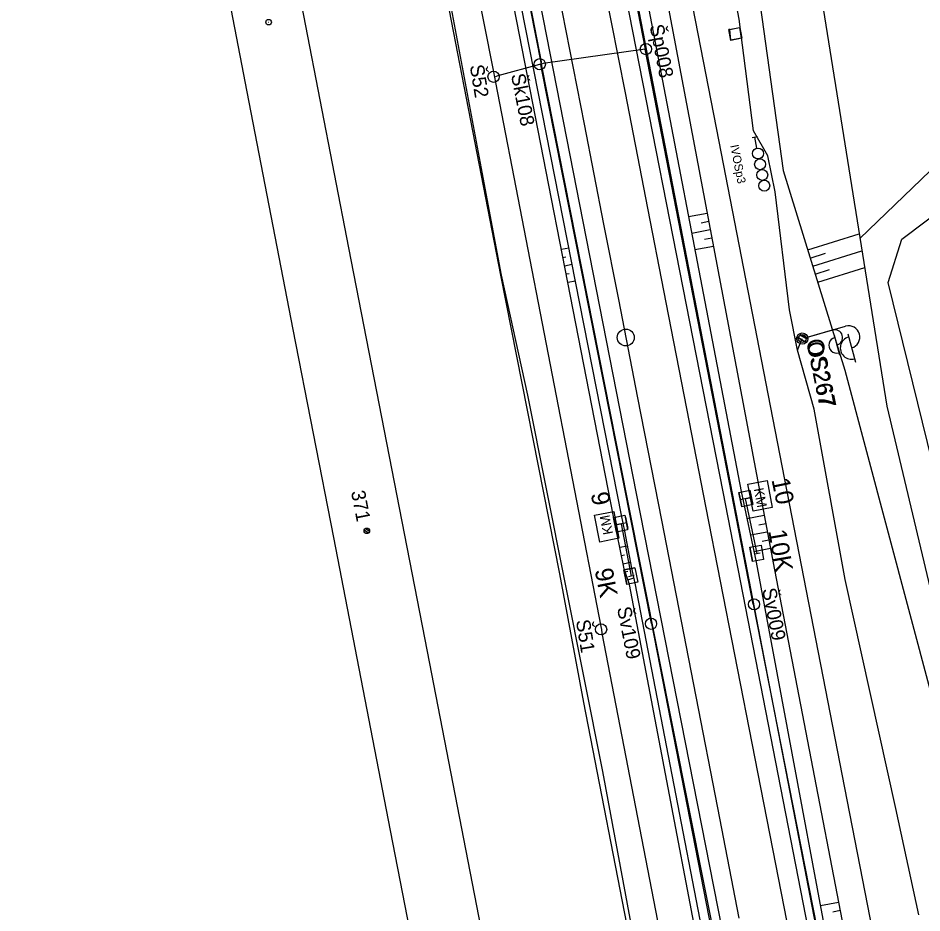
# Model space of a CAD drawing. Extents: x -545967 to -545044, y -1122650 to -1118491.
# Drawn here: x -545851.2 to -545770.8, y -1118840.2 to -1118760.6 of the extents above; entities that cross this region are included whole.
import ezdxf

# ---------------------------------------------------------------- set-up
doc = ezdxf.new("R2010")
doc.units = 0
for name, color, linetype in [('Vrstva 1', 7, 'Continuous'), ('Vrstva 1 - Koleje', 7, 'Continuous'), ('Vrstva 11', 7, 'Continuous'), ('Vrstva 11 - Trakce', 7, 'Continuous'), ('Vrstva 12', 7, 'Continuous'), ('Vrstva 12 - Trakce zaklady', 7, 'Continuous'), ('Vrstva 19 - Staniceni', 7, 'Continuous'), ('Vrstva 25', 7, 'Continuous'), ('Vrstva 25 - silnoproud prvky', 7, 'Continuous'), ('Vrstva 26', 7, 'Continuous'), ('Vrstva 26 - silnoproud', 7, 'Continuous'), ('Vrstva 28', 7, 'Continuous'), ('Vrstva 28 - zabzar', 7, 'Continuous'), ('Vrstva 32', 7, 'Continuous'), ('Vrstva 4 - Teren - stezky - prechody - plochy', 7, 'Continuous'), ('Vrstva 43', 7, 'Continuous'), ('Vrstva 44', 7, 'Continuous'), ('Vrstva 48', 7, 'Continuous'), ('Vrstva 49', 7, 'Continuous'), ('Vrstva 6', 7, 'Continuous'), ('Vrstva 62', 7, 'Continuous')]:
    doc.layers.add(name, color=color, linetype=linetype)

msp = doc.modelspace()

# ---------------------------------------------------------------- linework, layer by layer
at = {"layer": 'Vrstva 1'}
for points in [[(-545803.343, -1118697.361), (-545802.529, -1118701.559), (-545796.372, -1118733.137), (-545788.892, -1118771.626), (-545784.123, -1118796.192), (-545777.723, -1118829.089), (-545771.163, -1118862.699), (-545764.792, -1118895.381), (-545757.603, -1118932.309), (-545753.441, -1118953.648), (-545749.904, -1118971.286), (-545746.403, -1118987.4), (-545742.64, -1119003.664), (-545739.307, -1119017.411), (-545735.997, -1119030.103), (-545730.526, -1119049.438)], [(-545838.408, -1118714.766), (-545838.264, -1118718.348), (-545837.486, -1118728.28), (-545836.887, -1118733.389), (-545834.73, -1118746.875), (-545830.836, -1118767.188), (-545826.73, -1118788.319), (-545823.138, -1118806.831), (-545818.076, -1118832.894), (-545813.108, -1118858.452), (-545808.531, -1118881.987), (-545803.057, -1118910.121), (-545797.597, -1118938.248), (-545792.143, -1118966.396), (-545787.423, -1118990.652), (-545782.57, -1119015.553), (-545777.212, -1119042.997), (-545771.689, -1119071.297)], [(-545838.408, -1118714.766), (-545838.264, -1118718.348), (-545837.486, -1118728.28), (-545836.887, -1118733.389), (-545834.73, -1118746.875), (-545830.836, -1118767.188), (-545826.73, -1118788.319), (-545823.138, -1118806.831), (-545818.076, -1118832.894), (-545813.108, -1118858.452), (-545808.531, -1118881.987), (-545803.057, -1118910.121), (-545797.597, -1118938.248), (-545792.143, -1118966.396), (-545787.423, -1118990.652), (-545782.57, -1119015.553), (-545777.212, -1119042.997), (-545771.689, -1119071.297)], [(-545833.035, -1118722.987), (-545832.612, -1118725.218), (-545828.16, -1118748.155), (-545821.787, -1118781.064), (-545814.8, -1118816.973), (-545807.184, -1118856.232), (-545801.349, -1118886.259), (-545795.986, -1118913.812), (-545789.887, -1118945.221), (-545784.095, -1118975.016), (-545776.352, -1119014.883), (-545771.025, -1119042.195)]]:
    msp.add_lwpolyline(points, dxfattribs=at)
at = {"layer": 'Vrstva 1 - Koleje'}
for points in [[(-545809.67, -1118703.454), (-545807.882, -1118712.632), (-545806.03, -1118722.125), (-545804.223, -1118731.391), (-545802.337, -1118741.068), (-545800.493, -1118750.516), (-545799.063, -1118757.843), (-545797.222, -1118767.299), (-545795.407, -1118776.622), (-545793.591, -1118785.937), (-545791.761, -1118795.345), (-545790.039, -1118804.177), (-545787.497, -1118817.223), (-545785.692, -1118826.488), (-545783.856, -1118835.888), (-545781.902, -1118845.893)], [(-545812.52, -1118710.222), (-545810.747, -1118719.317), (-545808.924, -1118728.683), (-545807.065, -1118738.215), (-545804.558, -1118751.082), (-545802.792, -1118760.131), (-545800.853, -1118770.074), (-545799.124, -1118778.962), (-545797.814, -1118785.665), (-545796.111, -1118794.424), (-545793.992, -1118805.28), (-545790.937, -1118820.957), (-545789.005, -1118830.866), (-545787.094, -1118840.68)]]:
    msp.add_lwpolyline(points, dxfattribs=at)
at = {"layer": 'Vrstva 11'}
for p, q in [((-545820.029, -1118806.446), (-545820.407, -1118806.19)), ((-545819.921, -1118806.292), (-545820.305, -1118806.033))]:
    msp.add_line(p, q, dxfattribs=at)
msp.add_circle((-545820.163, -1118806.237), 0.25, dxfattribs=at)
at = {"layer": 'Vrstva 11 - Trakce'}
for p, q in [((-545787.097, -1118802.985), (-545786.892, -1118803.964)), ((-545786.118, -1118802.78), (-545785.913, -1118803.759)), ((-545786.016, -1118803.269), (-545786.994, -1118803.475)), ((-545785.473, -1118808.256), (-545786.505, -1118803.372)), ((-545798.152, -1118805.226), (-545797.959, -1118806.207)), ((-545797.171, -1118805.033), (-545796.978, -1118806.014)), ((-545797.074, -1118805.523), (-545798.056, -1118805.717)), ((-545797.565, -1118805.62), (-545796.668, -1118810.265)), ((-545785.224, -1118808.213), (-545785.716, -1118808.298)), ((-545796.42, -1118810.216), (-545796.91, -1118810.313))]:
    msp.add_line(p, q, dxfattribs=at)
at = {"layer": 'Vrstva 12'}
msp.add_line((-545787.822, -1118762.641), (-545788.002, -1118761.65), dxfattribs=at)
for points in [[(-545787.906, -1118761.663), (-545788.002, -1118761.65), (-545787.025, -1118761.482), (-545787.051, -1118761.467)], [(-545787.025, -1118761.482), (-545786.835, -1118762.42), (-545786.886, -1118762.435)], [(-545786.835, -1118762.42), (-545787.822, -1118762.641), (-545787.806, -1118762.593)]]:
    msp.add_lwpolyline(points, dxfattribs=at)
msp.add_lwpolyline([(-545787.906, -1118761.663), (-545787.051, -1118761.467), (-545786.886, -1118762.435), (-545787.806, -1118762.593)], close=True, dxfattribs=at)
at = {"layer": 'Vrstva 12 - Trakce zaklady'}
for p, q in [((-545787.117, -1118802.83), (-545786.138, -1118802.625)), ((-545785.871, -1118803.897), (-545786.85, -1118804.102)), ((-545798.231, -1118805.05), (-545797.25, -1118804.857)), ((-545796.994, -1118806.157), (-545797.975, -1118806.35)), ((-545786.122, -1118807.675), (-545785.137, -1118807.504)), ((-545784.913, -1118808.794), (-545785.898, -1118808.965)), ((-545796.339, -1118809.519), (-545797.32, -1118809.713)), ((-545796.084, -1118810.808), (-545797.065, -1118811.002))]:
    msp.add_line(p, q, dxfattribs=at)
for points in [[(-545786.85, -1118804.102), (-545787.117, -1118802.83), (-545786.138, -1118802.625), (-545785.871, -1118803.897), (-545786.85, -1118804.102)], [(-545787.117, -1118802.83), (-545787.117, -1118802.83), (-545786.85, -1118804.102), (-545786.85, -1118804.102)], [(-545786.138, -1118802.625), (-545786.138, -1118802.625), (-545785.871, -1118803.897), (-545785.871, -1118803.897)], [(-545797.25, -1118804.857), (-545796.994, -1118806.157), (-545797.975, -1118806.35), (-545798.231, -1118805.05), (-545797.25, -1118804.857)], [(-545798.231, -1118805.05), (-545798.231, -1118805.05), (-545797.975, -1118806.35), (-545797.975, -1118806.35)], [(-545797.25, -1118804.857), (-545797.25, -1118804.857), (-545796.994, -1118806.157), (-545796.994, -1118806.157)], [(-545785.898, -1118808.965), (-545786.122, -1118807.675), (-545785.137, -1118807.504), (-545784.913, -1118808.794), (-545785.898, -1118808.965)], [(-545786.122, -1118807.675), (-545786.122, -1118807.675), (-545785.898, -1118808.965), (-545785.898, -1118808.965)], [(-545785.137, -1118807.504), (-545785.137, -1118807.504), (-545784.913, -1118808.794), (-545784.913, -1118808.794)], [(-545796.339, -1118809.519), (-545796.084, -1118810.808), (-545797.065, -1118811.002), (-545797.32, -1118809.713), (-545796.339, -1118809.519)], [(-545797.32, -1118809.713), (-545797.32, -1118809.713), (-545797.065, -1118811.002), (-545797.065, -1118811.002)], [(-545796.339, -1118809.519), (-545796.339, -1118809.519), (-545796.084, -1118810.808), (-545796.084, -1118810.808)]]:
    msp.add_lwpolyline(points, dxfattribs=at)
at = {"layer": 'Vrstva 19 - Staniceni'}
for p, q in [((-545786.505, -1118803.372), (-545786.077, -1118803.289)), ((-545797.565, -1118805.62), (-545797.993, -1118805.704))]:
    msp.add_line(p, q, dxfattribs=at)
for points in [[(-545786.308, -1118802.092), (-545784.602, -1118801.762), (-545784.138, -1118804.159), (-545785.845, -1118804.489)], [(-545797.759, -1118806.9), (-545799.465, -1118807.233), (-545799.933, -1118804.837), (-545798.227, -1118804.504)]]:
    msp.add_lwpolyline(points, close=True, dxfattribs=at)
msp.add_circle((-545797.157, -1118789.046), 0.75, dxfattribs=at)
at = {"layer": 'Vrstva 25'}
for p, q in [((-545780.992, -1118789.001), (-545777.623, -1118788.05)), ((-545781.958, -1118789.026), (-545781.123, -1118789.493)), ((-545781.743, -1118788.717), (-545780.976, -1118789.146)), ((-545777.433, -1118788.724), (-545776.727, -1118791.226))]:
    msp.add_line(p, q, dxfattribs=at)
msp.add_circle((-545781.473, -1118789.137), 0.5, dxfattribs=at)
msp.add_circle((-545781.473, -1118789.137), 0.5, dxfattribs=at)
for centre, start, end in [((-545777.352, -1118789.013), 285.76362, 105.76362), ((-545777.092, -1118789.978), 105.06104, 286.46619)]:
    msp.add_arc(centre, 1, start, end, dxfattribs=at)
at = {"layer": 'Vrstva 25 - silnoproud prvky'}
for p, q in [((-545781.136, -1118789.042), (-545778.778, -1118788.376)), ((-545781.813, -1118789.059), (-545781.228, -1118789.386)), ((-545781.662, -1118788.843), (-545781.125, -1118789.143)), ((-545778.645, -1118788.848), (-545778.151, -1118790.599))]:
    msp.add_line(p, q, dxfattribs=at)
msp.add_circle((-545781.473, -1118789.137), 0.35, dxfattribs=at)
for centre, start, end in [((-545778.588, -1118789.05), 285.76362, 105.76362), ((-545778.406, -1118789.726), 105.06104, 286.46619)]:
    msp.add_arc(centre, 0.7, start, end, dxfattribs=at)
at = {"layer": 'Vrstva 26'}
for points in [[(-545771.097, -1118840.383), (-545773.141, -1118830.925), (-545777.672, -1118810.574), (-545780.401, -1118795.417), (-545781.883, -1118790.167), (-545782.61, -1118786.576), (-545783.878, -1118776.094), (-545784.515, -1118772.9), (-545785.804, -1118770.659), (-545787.081, -1118760.752), (-545789.369, -1118748.588), (-545791.737, -1118737.523), (-545792.399, -1118734.644), (-545793.816, -1118727.544), (-545794.532, -1118722.759), (-545794.625, -1118720.933), (-545795.14, -1118719.856), (-545797.401, -1118709.038)], [(-545781.883, -1118790.167), (-545781.473, -1118789.137)]]:
    msp.add_lwpolyline(points, dxfattribs=at)
at = {"layer": 'Vrstva 26 - silnoproud'}
for points in [[(-545804.723, -1118669.38), (-545823.422, -1118673.004), (-545824.024, -1118671.607), (-545826.19, -1118672.019), (-545826.479, -1118672.345), (-545826.082, -1118675.405), (-545825.636, -1118675.016), (-545825.253, -1118675.052), (-545825.524, -1118675.387), (-545825.985, -1118675.439), (-545827.078, -1118675.764), (-545828.843, -1118676.437), (-545828.656, -1118678.804), (-545827.868, -1118683.721), (-545826.321, -1118691.367), (-545821.946, -1118713.57), (-545816.92, -1118739.132), (-545813.046, -1118758.857), (-545808.289, -1118783.504), (-545803.049, -1118810.067), (-545800.897, -1118821.514), (-545796.684, -1118843.318)], [(-545771.097, -1118840.383), (-545773.141, -1118830.925), (-545777.672, -1118810.574), (-545780.401, -1118795.417), (-545781.883, -1118790.167), (-545782.61, -1118786.576), (-545783.878, -1118776.094), (-545784.515, -1118772.9), (-545785.804, -1118770.659), (-545787.081, -1118760.752), (-545789.369, -1118748.588), (-545791.737, -1118737.523), (-545792.399, -1118734.644), (-545793.816, -1118727.544), (-545794.532, -1118722.759), (-545794.625, -1118720.933), (-545795.14, -1118719.856), (-545797.401, -1118709.038)], [(-545781.883, -1118790.167), (-545781.473, -1118789.137)]]:
    msp.add_lwpolyline(points, dxfattribs=at)
at = {"layer": 'Vrstva 28'}
msp.add_line((-545828.914, -1118761.007), (-545828.864, -1118761.007), dxfattribs=at)
msp.add_circle((-545828.889, -1118761.007), 0.25, dxfattribs=at)
at = {"layer": 'Vrstva 28 - zabzar'}
msp.add_lwpolyline([(-545759.72, -1119031.91), (-545759.89, -1119030.77), (-545763.23, -1119013.33), (-545766.25, -1118997.62), (-545768.86, -1118984.55), (-545771, -1118974.69), (-545771.8, -1118970.9), (-545773.86, -1118959.07), (-545776.3, -1118946.17), (-545780.31, -1118924.98), (-545785.87, -1118897.11), (-545790.99, -1118870.65), (-545796.29, -1118843.25), (-545799.19, -1118827.63), (-545805.85, -1118794.17), (-545808.2, -1118783.5), (-545812.82, -1118758.82), (-545816.62, -1118739.16), (-545820.43, -1118719.58), (-545822.89, -1118707.67), (-545825.23, -1118696.09)], dxfattribs=at)
at = {"layer": 'Vrstva 32'}
msp.add_lwpolyline([(-545796.29, -1118843.25), (-545799.19, -1118827.63), (-545805.85, -1118794.17), (-545808.2, -1118783.5), (-545812.82, -1118758.82), (-545816.62, -1118739.16), (-545820.43, -1118719.58), (-545822.89, -1118707.67)], dxfattribs=at)
at = {"layer": 'Vrstva 4 - Teren - stezky - prechody - plochy'}
for points in [[(-545842.991, -1118523.919), (-545841.705, -1118530.396), (-545836.849, -1118554.447), (-545831.054, -1118584.604), (-545819.351, -1118645.264), (-545811.232, -1118686.911), (-545799.532, -1118746.647), (-545788.535, -1118802.768), (-545777.847, -1118857.696), (-545765.826, -1118919.341), (-545755.98, -1118970.183), (-545745.509, -1119023.121), (-545734.813, -1119078.883), (-545723.148, -1119138.675), (-545711.327, -1119199.256), (-545707.51, -1119218.932), (-545706.355, -1119218.803)], [(-545842.057, -1118523.737), (-545841.08, -1118528.803), (-545840.285, -1118532.869), (-545839.902, -1118534.493), (-545835.95, -1118554.692), (-545830.173, -1118584.852), (-545827.402, -1118599.381), (-545819.669, -1118640.626), (-545818.68, -1118644.829), (-545817.556, -1118652.409), (-545817.153, -1118653.253), (-545814.795, -1118664.646), (-545810.716, -1118686.202), (-545798.466, -1118747.292), (-545787.709, -1118802.92), (-545777.141, -1118857.583)], [(-545711.324, -1119247.435), (-545711.901, -1119243.963), (-545720.224, -1119201.665), (-545721.285, -1119195.757), (-545731.546, -1119141.712), (-545737.081, -1119112.42), (-545743.441, -1119079.103), (-545754.278, -1119022.005), (-545764.127, -1118971.243), (-545774.702, -1118917.119), (-545786.098, -1118858.181), (-545797.005, -1118803.413), (-545807.661, -1118749.422), (-545819.911, -1118686.431), (-545828.531, -1118641.36), (-545850.15, -1118530.525), (-545851.156, -1118525.517)], [(-545710.225, -1119247.22), (-545719.004, -1119201.386), (-545730.622, -1119141.385), (-545736.208, -1119112.206), (-545742.564, -1119078.927), (-545753.414, -1119021.814), (-545763.359, -1118970.942), (-545773.922, -1118916.709), (-545785.328, -1118858.188), (-545796.206, -1118802.914), (-545806.845, -1118748.63), (-545819.206, -1118686.191), (-545827.818, -1118641.013), (-545849.345, -1118530.249), (-545850.409, -1118525.371)]]:
    msp.add_lwpolyline(points, dxfattribs=at)
at = {"layer": 'Vrstva 43'}
for centre in [(-545795.361, -1118763.396), (-545804.8, -1118764.75), (-545808.903, -1118765.858), (-545785.757, -1118812.77), (-545794.909, -1118814.497), (-545799.351, -1118814.994)]:
    msp.add_circle(centre, 0.5, dxfattribs=at)
at = {"layer": 'Vrstva 44'}
for points in [[(-545846.223, -1118571.979), (-545846.221, -1118572.119), (-545836.892, -1118620.467), (-545827.979, -1118669.157), (-545827.809, -1118669.462), (-545827.871, -1118669.728), (-545818.616, -1118716.33), (-545818.55, -1118716.796), (-545818.473, -1118717.196), (-545808.913, -1118765.432), (-545808.826, -1118765.882), (-545808.745, -1118766.383), (-545799.375, -1118814.752), (-545799.301, -1118815.001), (-545799.29, -1118815.321), (-545789.933, -1118863.748)], [(-545805.038, -1118714.002), (-545795.436, -1118763.417), (-545804.505, -1118764.688), (-545804.688, -1118764.766)], [(-545814.194, -1118715.513), (-545804.66, -1118764.526), (-545804.688, -1118764.766)], [(-545785.83, -1118812.749), (-545795.436, -1118763.417)], [(-545804.688, -1118764.766), (-545804.811, -1118764.763), (-545808.514, -1118765.772), (-545808.826, -1118765.882)], [(-545794.86, -1118814.466), (-545804.65, -1118765.092), (-545804.688, -1118764.766)], [(-545785.83, -1118812.749), (-545776.282, -1118861.269), (-545785.186, -1118863.215), (-545785.429, -1118863.254)], [(-545794.86, -1118814.466), (-545785.374, -1118863.065), (-545785.429, -1118863.254)]]:
    msp.add_lwpolyline(points, dxfattribs=at)
at = {"layer": 'Vrstva 48'}
for p, q in [((-545789.919, -1118778.005), (-545791.571, -1118778.317)), ((-545789.78, -1118778.742), (-545790.44, -1118778.867)), ((-545789.641, -1118779.48), (-545791.289, -1118779.79)), ((-545789.502, -1118780.217), (-545790.161, -1118780.341)), ((-545780.986, -1118781.259), (-545776.402, -1118779.841)), ((-545802.88, -1118781.189), (-545802.212, -1118781.058)), ((-545789.364, -1118780.954), (-545791.007, -1118781.263)), ((-545802.736, -1118781.925), (-545802.469, -1118781.873)), ((-545780.764, -1118781.976), (-545779.42, -1118781.56)), ((-545780.542, -1118782.692), (-545776.163, -1118781.337)), ((-545802.592, -1118782.661), (-545801.923, -1118782.53)), ((-545780.099, -1118784.125), (-545775.923, -1118782.833)), ((-545802.448, -1118783.397), (-545802.181, -1118783.345)), ((-545780.321, -1118783.409), (-545779.037, -1118783.012)), ((-545802.305, -1118784.133), (-545801.634, -1118784.002)), ((-545784.856, -1118804.867), (-545786.387, -1118805.156)), ((-545784.717, -1118805.604), (-545785.323, -1118805.719)), ((-545784.578, -1118806.341), (-545786.077, -1118806.624)), ((-545797.693, -1118807.7), (-545797.006, -1118807.56)), ((-545784.3, -1118807.815), (-545785.767, -1118808.092)), ((-545784.439, -1118807.078), (-545785.032, -1118807.19)), ((-545797.544, -1118808.435), (-545797.272, -1118808.38)), ((-545797.394, -1118809.17), (-545796.725, -1118809.034)), ((-545797.207, -1118809.895), (-545796.963, -1118809.81)), ((-545796.961, -1118810.603), (-545796.431, -1118810.419)), ((-545778.252, -1118839.271), (-545779.857, -1118839.58)), ((-545778.11, -1118840.008), (-545778.754, -1118840.132))]:
    msp.add_line(p, q, dxfattribs=at)
at = {"layer": 'Vrstva 49'}
for points in [[(-545839.308, -1118523.198), (-545838.102, -1118529.579), (-545837.4, -1118533.485), (-545832.706, -1118555.695), (-545825.144, -1118594.377), (-545814.251, -1118651.352), (-545808.026, -1118685.152), (-545795.162, -1118750.192), (-545783.943, -1118809.71), (-545774.848, -1118856.951), (-545763.418, -1118915.038), (-545752.928, -1118968.655), (-545741.707, -1119025.946), (-545730.219, -1119081.986), (-545719.001, -1119141.326), (-545708.857, -1119196.833), (-545704.642, -1119214.146)], [(-545841.458, -1118523.619), (-545840.502, -1118528.796), (-545840.206, -1118530.169), (-545839.525, -1118532.718), (-545839.264, -1118534.264), (-545835.124, -1118554.723), (-545829.514, -1118584.885), (-545827.92, -1118592.873), (-545827.648, -1118594.262), (-545826.635, -1118599.217), (-545819.032, -1118640.374), (-545818.68, -1118644.829), (-545817.556, -1118652.409), (-545816.515, -1118653.065), (-545813.954, -1118664.567), (-545810.048, -1118684.976), (-545808.757, -1118691.228), (-545797.462, -1118748.583), (-545796.998, -1118749.953), (-545786.899, -1118802.732), (-545785.57, -1118809.023), (-545776.461, -1118857.744)], [(-545787.565, -1118859.78), (-545796.822, -1118811.001), (-545797.303, -1118809.619), (-545797.956, -1118806.406), (-545798.235, -1118804.969), (-545808.533, -1118752.244), (-545808.823, -1118750.705), (-545820.011, -1118693.395), (-545820.267, -1118691.79), (-545820.94, -1118688.496), (-545821.249, -1118687.074), (-545823.077, -1118678.082), (-545823.606, -1118676.864), (-545824.251, -1118676.389)], [(-545786.924, -1118859.548), (-545796.323, -1118810.897), (-545796.625, -1118809.56), (-545797.25, -1118806.278), (-545797.544, -1118804.841), (-545807.893, -1118752.116), (-545808.138, -1118750.544), (-545819.301, -1118693.257), (-545819.514, -1118691.615), (-545820.246, -1118688.348), (-545820.472, -1118686.892), (-545821.991, -1118678.267), (-545823.152, -1118676.433), (-545824.251, -1118676.389)], [(-545790.558, -1118698.682), (-545783.238, -1118737.17), (-545773.95, -1118795.15), (-545740.894, -1118934.351)], [(-545795.7, -1118699.528), (-545788.233, -1118737.742), (-545783.17, -1118774.198), (-545777.676, -1118791.958), (-545766.252, -1118834.896), (-545762.229, -1118863.517), (-545750.538, -1118910.15), (-545748.755, -1118933.679), (-545738.226, -1118978.242), (-545734.453, -1118993.366), (-545726.802, -1119029.271), (-545708.682, -1119069.733), (-545699.17, -1119099.963), (-545685.313, -1119124.181), (-545683.358, -1119136.056), (-545688.074, -1119145.796), (-545688.341, -1119153.091)]]:
    msp.add_lwpolyline(points, dxfattribs=at)
at = {"layer": 'Vrstva 6'}
for p, q in [((-545785.439, -1118771.189), (-545785.93, -1118771.284)), ((-545785.495, -1118772.208), (-545785.684, -1118771.237))]:
    msp.add_line(p, q, dxfattribs=at)
for centre in [(-545785.402, -1118772.685), (-545785.216, -1118773.638), (-545785.03, -1118774.591), (-545784.845, -1118775.544)]:
    msp.add_circle(centre, 0.486, dxfattribs=at)
at = {"layer": 'Vrstva 62'}
for points in [[(-545757.828, -1118774.611), (-545765.411, -1118769.726), (-545776.341, -1118780.227)], [(-545713.693, -1118793.649), (-545714.955, -1118797.921), (-545737.065, -1118808.497), (-545752.226, -1118819.242), (-545760.185, -1118827.008), (-545763.755, -1118825.16), (-545773.831, -1118784.141), (-545772.626, -1118780.296), (-545766.261, -1118775.492), (-545761.347, -1118777.62), (-545760.649, -1118780.978)]]:
    msp.add_lwpolyline(points, dxfattribs=at)

# ---------------------------------------------------------------- texts
at = {"layer": 'Vrstva 11'}
msp.add_text('371', height=1.25, rotation=281.01076, dxfattribs=at).set_placement((-545821.577, -1118802.756))
at = {"layer": 'Vrstva 11 - Trakce'}
for s, rotation, p in [('10', 281.8546, (-545784.212, -1118801.684)), ('9', 281.14032, (-545800.275, -1118802.932)), ('10K', 279.85081, (-545784.497, -1118806.235)), ('9K', 281.19021, (-545799.924, -1118809.712))]:
    msp.add_text(s, height=1.6, rotation=rotation, dxfattribs=at).set_placement(p)
at = {"layer": 'Vrstva 19 - Staniceni'}
for rotation, p in [(280.942, (-545785.787, -1118802.508)), (101.04478, (-545798.282, -1118806.485))]:
    msp.add_text('KM', height=0.8728, rotation=rotation, dxfattribs=at).set_placement(p)
at = {"layer": 'Vrstva 25'}
msp.add_text('OS267', height=1.5, rotation=281.44488, dxfattribs=at).set_placement((-545781.136, -1118789.306))
at = {"layer": 'Vrstva 25 - silnoproud prvky'}
msp.add_text('OS267', height=1.4, rotation=281.44488, dxfattribs=at).set_placement((-545781.077, -1118789.548))
at = {"layer": 'Vrstva 43'}
for s, rotation, p in [('Šp008', 280.99979, (-545795.041, -1118761.31)), ('Š52', 279.31701, (-545811.021, -1118764.873)), ('Šk108', 280.99979, (-545807.36, -1118765.684)), ('Šv009', 280.99979, (-545785.041, -1118811.434)), ('Šv109', 280.99979, (-545797.937, -1118813.091)), ('Š51', 279.31701, (-545801.589, -1118814.219))]:
    msp.add_text(s, height=1.25, rotation=rotation, dxfattribs=at).set_placement(p)
at = {"layer": 'Vrstva 6'}
msp.add_text('IVOSp3', height=0.75, rotation=280.98619, dxfattribs=at).set_placement((-545787.876, -1118771.967))

doc.saveas('drawing.dxf')
